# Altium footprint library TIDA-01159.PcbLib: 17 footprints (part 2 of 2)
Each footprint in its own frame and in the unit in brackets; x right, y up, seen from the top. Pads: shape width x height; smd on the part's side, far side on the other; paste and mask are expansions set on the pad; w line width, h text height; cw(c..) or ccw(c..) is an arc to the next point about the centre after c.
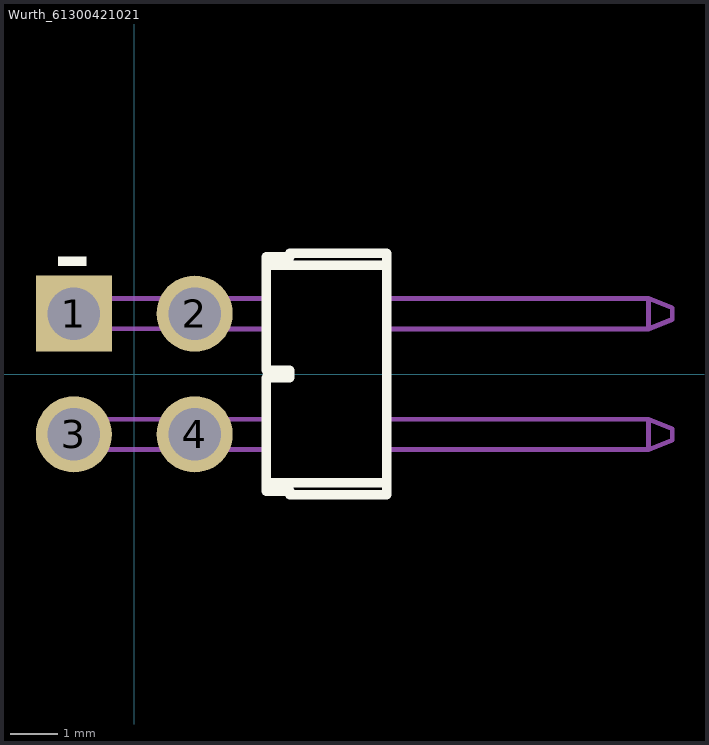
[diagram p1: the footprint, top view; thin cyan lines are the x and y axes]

## Wurth_61300421021 [mm] "Header, 2.54mm, 2x2, R/A, TH"
height 5.23
pads (4):
  rect 1.6x1.6 hole 1.1: 1(-1.27,1.27)
  round 1.6 hole 1.1: 2(1.27,1.27) 3(-1.27,-1.27) 4(1.27,-1.27)
Top Overlay:
  rectangle: -1.6,2.27 -1,2.47
  lines w0.2: 2.77,-2.29 5.31,-2.29 ; 2.77,-2.29 2.77,-2.46 3.27,-2.46 3.27,-2.54 5.31,-2.54 5.31,-2.29 ; 2.77,-2.29 2.77,-0.25 2.77,-0.08 3.27,-0.08 3.27,0 3.27,0.08 2.77,0.08 2.77,0.25 2.77,2.29 ; 2.77,2.29 5.31,2.29 ; 2.77,2.29 2.77,2.46 3.27,2.46 3.27,2.54 5.31,2.54 5.31,2.29 ; 5.31,-2.29 5.31,-0.25 5.31,0 5.31,0.25 5.31,2.29
Mechanical 5:
  lines w0.1: 0.95,-1.59 0.95,-1.595 1.79,-1.595 2.77,-1.595 ; 0.95,0.95 0.95,0.945 1.79,0.945 2.77,0.945 ; 2.77,-1.59 -0.75,-1.59 -1.59,-1.59 -1.59,-0.95 -0.75,-0.95 2.77,-0.95 ; 2.77,0.95 -0.75,0.95 -1.59,0.95 -1.59,1.59 -0.75,1.59 2.77,1.59 ; 5.31,-1.595 10.81,-1.595 ; 5.31,-1.59 10.81,-1.59 ; 5.31,-0.95 10.81,-0.95 ; 5.31,0.945 10.81,0.945 ; 5.31,0.95 10.81,0.95 ; 5.31,1.59 10.81,1.59 ; 2.77,-2.29 2.77,-0.25 2.77,-0.08 3.27,-0.08 3.27,0 3.27,0.08 2.77,0.08 2.77,0.25 2.77,2.29 ; 2.77,-2.29 2.77,-2.46 3.27,-2.46 3.27,-2.54 5.31,-2.54 5.31,-2.29 ; 2.77,-2.29 5.31,-2.29 ; 2.77,2.29 2.77,2.46 3.27,2.46 3.27,2.54 5.31,2.54 5.31,2.29 ; 2.77,2.29 5.31,2.29 ; 5.31,-2.29 5.31,-0.25 5.31,0 5.31,0.25 5.31,2.29 ; 10.81,-1.595 10.81,-1.59 ; 10.81,-1.595 11.31,-1.395 11.31,-1.39 ; 10.81,-1.59 10.81,-0.95 ; 10.81,-1.59 11.31,-1.39 ; 10.81,-0.95 11.31,-1.15 11.31,-1.39 ; 10.81,0.945 10.81,0.95 ; 10.81,0.945 11.31,1.145 11.31,1.15 ; 10.81,0.95 10.81,1.59 ; 10.81,0.95 11.31,1.15 ; 10.81,1.59 11.31,1.39 11.31,1.15
  text ".Designator" at 4.496,-0.61 h0.76
3D body: height 5.08, standoff -3, extent -1.59,-2.54 11.31,2.54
